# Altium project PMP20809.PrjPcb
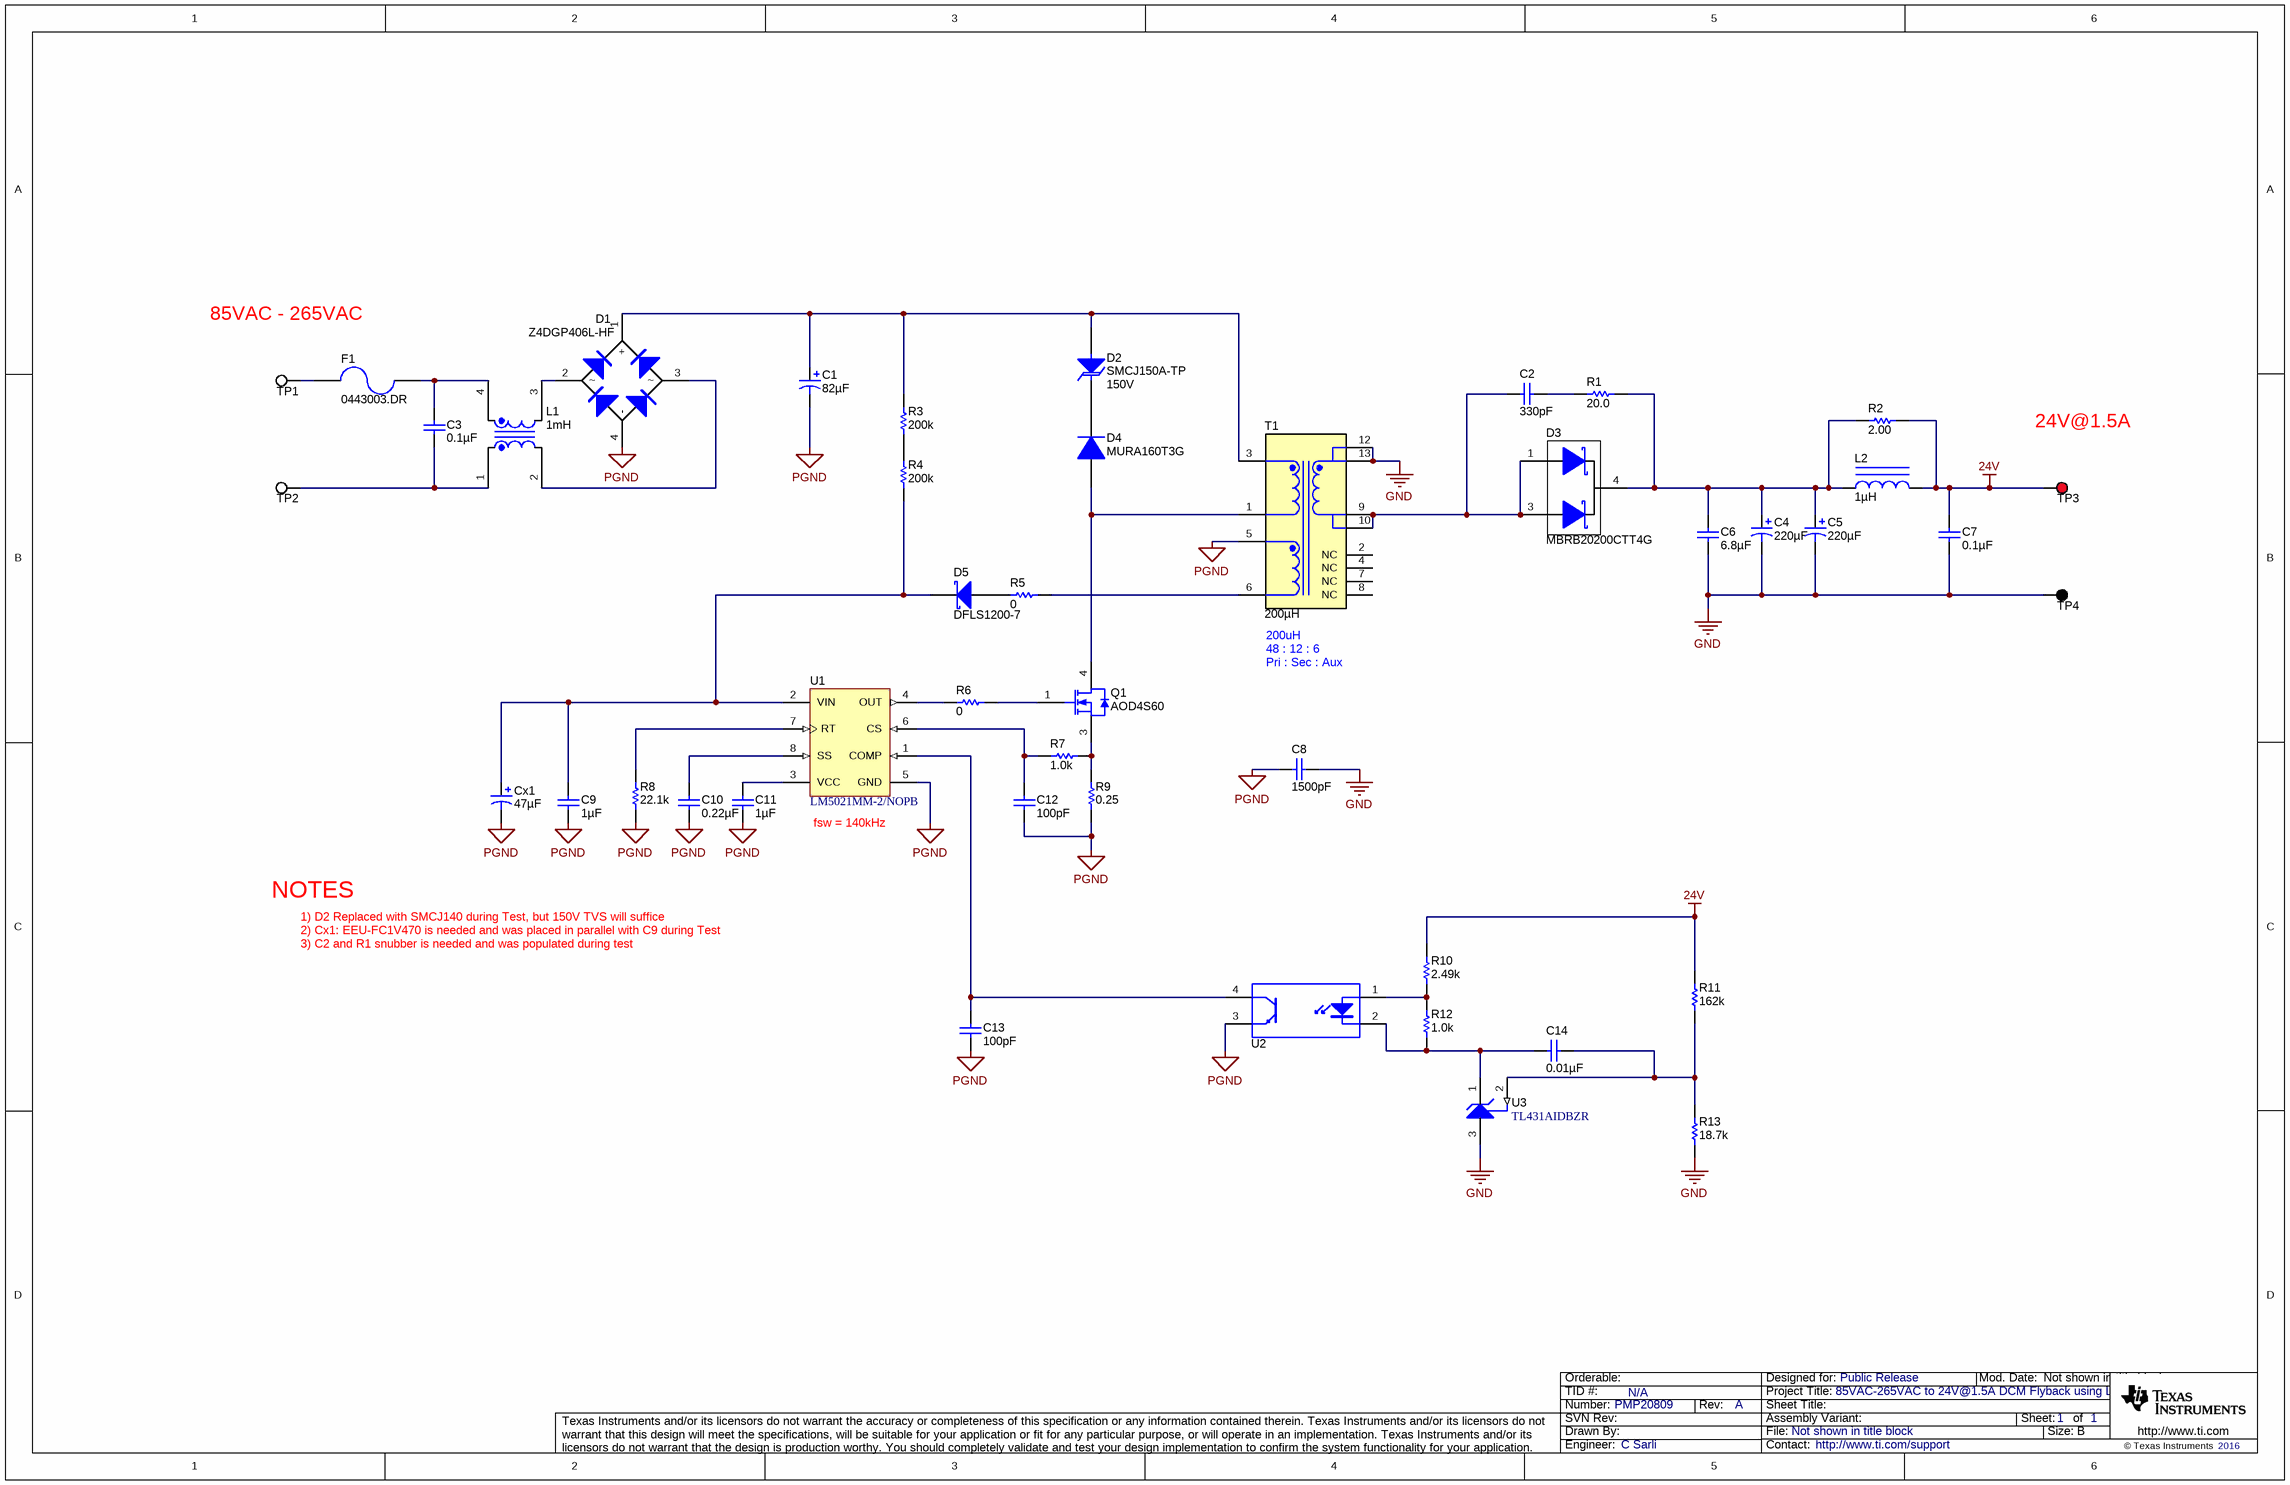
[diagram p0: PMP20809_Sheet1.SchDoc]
CopyrightYear: 2016; PCB_Layout: C Sarli; PCB_Rev: A; PRJ_Customer: Public Release; PRJ_Engineer: C Sarli; PRJ_Number: PMP20809; PRJ_Title: 85VAC-265VAC to 24V@1.5A DCM Flyback using LM5021; SCH_Rev: A; TechSupport: http://www.ti.com/support; TID: N/A
1 sheet, 45 parts. Net scope: global (net labels, ports and power ports of the same name join across sheets).
Board file: PMP20809_PCB.PcbDoc

## Sheet PMP20809_Sheet1.SchDoc
size 431 x 279 mm; Date: Not shown in title block; ApprovedBy: Not shown in title block; CheckedBy: Not shown in title block; Author: Not shown in title block; CompanyName: Not shown in title block; Engineer: Not shown in title block; Organization: Not shown in title block; Address1: Not shown in title block; Address2: Not shown in title block; Address3: Not shown in title block; Address4: Not shown in title block; DocumentNumber: 1; Revision: Use project parameter SCH_Rev; SheetNumber: 1; SheetTotal: 1; PageSetup: Record=PageOptions¦CenterHorizontal=True¦CenterVertical=True¦PrintScale=1.00¦XCorrection=1.00¦YCorrection=1.00¦PrintKind=0¦BorderSize=5000000¦LeftOffset=0¦BottomOffset=0¦Orientation=2¦PaperLength=1000¦PaperWidth=1000¦Scale=100¦PaperSource=15¦PrintQuality=600¦MediaType=1¦DitherType=10¦PaperKind=Letter¦PrintScaleMode=1

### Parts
C1  ValueDisplayed: 82µF  [Nichicon_2200x2500_Snap]  (hidden comment: LLS2G820MELZ)
C2  ValueDisplayed: 330pF  [1206]  (hidden comment: GRM31A5C2J331JW01D)
C3  ValueDisplayed: 0.1µF  [WCAP-FTX2_1800x600x1200]  (hidden comment: 890324025017)
C4  ValueDisplayed: 220µF  [Chemi-Con_1000x1250]  (hidden comment: EKZE350ELL221MJC5S)
C5  ValueDisplayed: 220µF  [Chemi-Con_1000x1250]  (hidden comment: EKZE350ELL221MJC5S)
C6  ValueDisplayed: 6.8µF  [0805_HV]  (hidden comment: C2012X5R1V685K125AC)
C7  ValueDisplayed: 0.1µF  [0603]  (hidden comment: C1608X5R1H104K080AA)
C8  ValueDisplayed: 1500pF  [KY_700x500x1000]  (hidden comment: DE2E3KY152MN3AM02F)
C9  ValueDisplayed: 1µF  [0603]  (hidden comment: GRM188R61H105KAALD)
C10  ValueDisplayed: 0.22µF  [0402]  (hidden comment: GRM155R71C224KA12D)
C11  ValueDisplayed: 1µF  [0402]  (hidden comment: GRM155R61E105KA12D)
C12  ValueDisplayed: 100pF  [0402]  (hidden comment: GRM1555C1H101JA01D)
C13  ValueDisplayed: 100pF  [0402]  (hidden comment: GRM1555C1H101JA01D)
C14  ValueDisplayed: 0.01µF  [0402]  (hidden comment: GRM155R71H103KA88D)
Cx1  ValueDisplayed: 47µF  [FC_630x1120]  (hidden comment: EEU-FC1V470)
D1  Z4DGP406L-HF  [Z4-D]
D2  SMCJ150A-TP  value 150V  [SMC]
D3  MBRB20200CTT4G  [DDPAK]
D4  MURA160T3G  [SMA]
D5  DFLS1200-7  [PowerDI123]
F1  0443003.DR  [FUSE_0443]
L1  ValueDisplayed: 1mH  [WE-CMB_XS]  (hidden comment: 744821201)
L2  ValueDisplayed: 1µH  [B82462G4]  (hidden comment: B82462G4102M)
Q1  AOD4S60  [DPAK]
R1  ValueDisplayed: 20.0  [1206]  (hidden comment: CRCW120620R0FKEA)
R2  ValueDisplayed: 2.00  [1206]  (hidden comment: CRCW12062R00FKEA)
R3  ValueDisplayed: 200k  [2010]  (hidden comment: CRCW2010200KJNEF)
R4  ValueDisplayed: 200k  [2010]  (hidden comment: CRCW2010200KJNEF)
R5  ValueDisplayed: 0  [0402]  (hidden comment: CRCW04020000Z0ED)
R6  ValueDisplayed: 0  [0603]  (hidden comment: CRCW06030000Z0EA)
R7  ValueDisplayed: 1.0k  [0402]  (hidden comment: CRCW04021K00JNED)
R8  ValueDisplayed: 22.1k  [0402]  (hidden comment: CRCW040222K1FKED)
R9  ValueDisplayed: 0.25  [1206]  (hidden comment: CSR1206FKR250)
R10  ValueDisplayed: 2.49k  [0402]  (hidden comment: CRCW04022K49FKED)
R11  ValueDisplayed: 162k  [0402]  (hidden comment: CRCW0402162KFKED)
R12  ValueDisplayed: 1.0k  [0603]  (hidden comment: CRCW06031K00JNEA)
R13  ValueDisplayed: 18.7k  [0402]  (hidden comment: CRCW040218K7FKED)
T1  ValueDisplayed: 200µH  [Renco_RLTI-1228]  (hidden comment: RLTI-1228)
TP1  5012  [Keystone5012]  (value not drawn)
TP2  5012  [Keystone5012]  (value not drawn)
TP3  5010  [Keystone5010]  (value not drawn)
TP4  5011  [Keystone5011]  (value not drawn)
U1  LM5021MM-2/NOPB  [MUA08A_N]
U2  VOS617A-7X001T  [SSOP-4_VISHAY]  (value not drawn)
U3  TL431AIDBZR  [DBZ0003A_N]

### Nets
24V: C7.1 L2.2 R2.2 R10.2 R11.2 TP3.1
GND: C4.2(-) C5.2(-) C6.2 C7.2 C8.1 R13.1 T1.12 T1.13 TP4.1 U3.3(ANODE)
PGND: C1.2(-) C8.2 C9.2 C10.2 C11.2 C12.2 C13.2 Cx1.2(-) D1.4(-) R8.1 R9.1 T1.5 U1.5(GND) U2.3(E)
NetC1_1: C1.1(+) D1.1(+) D2.2(A) R3.2 T1.3
NetC2_1: C2.1 R1.1
NetC2_2: C2.2 D3.1(A) D3.3(A) T1.9 T1.10
NetC3_1: C3.1 F1.1 L1.4
NetC3_2: C3.2 L1.1 TP2.1
NetC4_1: C4.1(+) C5.1(+) C6.1 D3.4(K) L2.1 R1.2 R2.1
NetC9_1: C9.1 Cx1.1(+) D5.1(K) R4.1 U1.2(VIN)
NetC10_1: C10.1 U1.8(SS)
NetC11_1: C11.1 U1.3(VCC)
NetC12_1: C12.1 R7.1 U1.6(CS)
NetC13_1: C13.1 U1.1(COMP) U2.4(C)
NetC14_1: C14.1 R11.1 R13.2 U3.2(REF)
NetC14_2: C14.2 R12.1 U2.2(K) U3.1(CATHODE)
NetD1_2: D1.2 L1.3
NetD1_3: D1.3 L1.2
NetD2_1: D2.1(K) D4.1(K)
NetD4_2: D4.2(A) Q1.4(D) T1.1
NetD5_2: D5.2(A) R5.1
NetF1_2: F1.2 TP1.1
NetQ1_1: Q1.1(G) R6.2
NetQ1_3: Q1.3(S) R7.2 R9.2
NetR3_1: R3.1 R4.2
NetR5_2: R5.2 T1.6
NetR6_1: R6.1 U1.4(OUT)
NetR8_2: R8.2 U1.7(RT)
NetR10_1: R10.1 R12.2 U2.1(A)

Not connected (* = marked no-connect by the designer): T1 2(NC) 4(NC) 7(NC) 8(NC)

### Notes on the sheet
- 85VAC - 265VAC
- 24V@1.5A
- (near T1) 200uH
- (near T1) 48 : 12 : 6
- Pri : Sec : Aux
- (near U1) fsw = 140kHz
- NOTES
- 1) D2 Replaced with SMCJ140 during Test, but 150V TVS will suffice
- 2) Cx1: EEU-FC1V470 is needed and was placed in parallel with C9 during Test
- 3) C2 and R1 snubber is needed and was populated during test

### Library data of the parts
C1 = LLS2G820MELZ: CAP, AL, 82 µF, 400 V, +/- 20%, TH; Manufacturer: Nichicon; Polarized: Y; CompType: Capacitor; Value: 82uF; U/M: EA; Cap_F: 0.000082; Tolerance_%: 20; Value1: Unknown; VDC_V: 400; Value2: 400V; IRMS_A: 0.84; TaMin_C: -25; TaMax_C: 85; Cap_Case: 22x25mm; SizeAreaWB_mm2: 576; SizeArea_mm2: 484; SizeX_mm: 22; SizeZ_mm: 27; AEC Category: Q200; AEC Qualified: N
C2 = GRM31A5C2J331JW01D: CAP, CERM, 330 pF, 630 V, +/- 5%, C0G/NP0, 1206; Manufacturer: MuRata; Polarized: N; CompType: Capacitor; Value: 330pF; U/M: EA; Cap_F: 0.00000000033; Tolerance_%: 5; Value1: Unknown; VDC_V: 630; Value2: 630V; TaMin_C: -55; TaMax_C: 125; SizeArea_mm2: 5.12; SizeAreaWB_mm2: 10.92; SizeX_mm: 3.2; SizeY_mm: 1.6; SizeZ_mm: 1.35; AEC Category: Q200
C3 = 890324025017: CAP, Film, 0.1 µF, 275 V, +/- 10%, TH; Manufacturer: Wurth Elektronik; Polarized: N; CompType: Capacitor; Value: 0.1uF; U/M: EA; Cap_F: 0.0000001; Tolerance_%: 10; Value1: Unknown; VDC_V: 275; Value2: 275V; TaMin_C: -40; TaMax_C: 105; Cap_Case: 18x6x12mm; AEC Category: Q200
C4 C5 = EKZE350ELL221MJC5S: CAP, AL, 220 µF, 35 V, +/- 20%, TH; Manufacturer: Chemi-Con; Polarized: Y; CompType: Capacitor; Value: 220uF; U/M: EA; Cap_F: 0.00022; Tolerance_%: 20; Value1: Unknown; VDC_V: 35; Value2: 35V; IRMS_A: 1.03; TaMin_C: -40; TaMax_C: 105; Cap_Case: 10x12.5; SizeAreaWB_mm2: 144; SizeArea_mm2: 100; SizeX_mm: 10; SizeZ_mm: 14; AEC Category: Q200; AEC Qualified: N
C6 = C2012X5R1V685K125AC: CAP, CERM, 6.8 µF, 35 V, +/- 10%, X5R, 0805; Manufacturer: TDK; Polarized: N; CompType: Capacitor; Value: 6.8uF; U/M: EA; Cap_F: 0.0000068; Tolerance_%: 10; ESR_ohm: 0.003795; Value1: 0.003795 ohm; VDC_V: 35; Value2: 35V; IRMS_A: 3.34931; TaMin_C: -55; TaMax_C: 85; Cap_Case: 0805; SizeArea_mm2: 2.5; SizeAreaWB_mm2: 6.75; SizeX_mm: 2; SizeY_mm: 1.25; SizeZ_mm: 1.45; AEC Category: Q200
C7 = C1608X5R1H104K080AA: CAP, CERM, 0.1 µF, 50 V, +/- 10%, X5R, 0603; Manufacturer: TDK; Polarized: N; CompType: Capacitor; Value: 0.1uF; U/M: EA; Cap_F: 0.0000001; Tolerance_%: 10; ESR_ohm: 0.0296; Value1: 0.0296 ohm; VDC_V: 50; Value2: 50V; IRMS_A: 0.97199; TaMin_C: -55; TaMax_C: 85; SizeArea_mm2: 1.28; SizeAreaWB_mm2: 4.68; SizeX_mm: 1.6; SizeY_mm: 0.8; SizeZ_mm: 1; AEC Category: Q200
C8 = DE2E3KY152MN3AM02F: CAP, CERM, 1500 pF,  V, +/- 20%, E, TH, 2- Leads, Body 7x5mm, Pin Spacing 7.5mm; Manufacturer: MuRata; Polarized: N; CompType: Capacitor; Value: 1500pF; U/M: EA; Cap_F: 0.0000000015; Tolerance_%: 20; Value1: Unknown; TaMin_C: -25; TaMax_C: 85; Cap_Case: 7x5x10mm; SizeArea_mm2: 37.5; SizeAreaWB_mm2: 66.5; SizeX_mm: 7.5; SizeY_mm: 5; SizeZ_mm: 10; AEC Category: Q200
C9 = GRM188R61H105KAALD: CAP, CERM, 1 µF, 50 V, +/- 10%, X5R, 0603; Manufacturer: MuRata; Polarized: N; CompType: Capacitor; Value: 1uF; U/M: EA; Cap_F: 0.000001; Tolerance_%: 10; Value1: Unknown; VDC_V: 50; Value2: 50V; TaMin_C: -55; TaMax_C: 85; SizeArea_mm2: 1.28; SizeAreaWB_mm2: 4.68; SizeX_mm: 1.6; SizeY_mm: 0.8; SizeZ_mm: 1; AEC Category: Q200
C10 = GRM155R71C224KA12D: CAP, CERM, 0.22 µF, 16 V, +/- 10%, X7R, 0402; Manufacturer: MuRata; Polarized: N; CompType: Capacitor; Value: 0.22uF; U/M: EA; Cap_F: 0.00000022; Tolerance_%: 10; Value1: Unknown; VDC_V: 16; Value2: 16V; TaMin_C: -55; TaMax_C: 125; SizeArea_mm2: 0.5; SizeAreaWB_mm2: 3; SizeX_mm: 1; SizeZ_mm: 0.6; AEC Category: Q200
C11 = GRM155R61E105KA12D: CAP, CERM, 1 µF, 25 V, +/- 10%, X5R, 0402; Manufacturer: MuRata; Polarized: N; CompType: Capacitor; Value: 1uF; U/M: EA; Cap_F: 0.000001; Tolerance_%: 10; Value1: Unknown; VDC_V: 25; Value2: 25V; TaMin_C: -55; TaMax_C: 85; SizeArea_mm2: 0.5; SizeAreaWB_mm2: 3; SizeX_mm: 1; SizeZ_mm: 0.6; AEC Category: Q200
C12 C13 = GRM1555C1H101JA01D: CAP, CERM, 100 pF, 50 V, +/- 5%, C0G/NP0, 0402; Manufacturer: MuRata; Polarized: N; CompType: Capacitor; Value: 100pF; U/M: EA; Cap_F: 0.0000000001; Tolerance_%: 5; Value1: Unknown; VDC_V: 50; Value2: 50V; TaMin_C: -55; TaMax_C: 125; SizeArea_mm2: 0.5; SizeAreaWB_mm2: 3; SizeX_mm: 1; SizeZ_mm: 0.6; AEC Category: Q200
C14 = GRM155R71H103KA88D: CAP, CERM, 0.01 µF, 50 V, +/- 10%, X7R, 0402; Manufacturer: MuRata; Polarized: N; CompType: Capacitor; Value: 0.01uF; U/M: EA; Cap_F: 0.00000001; Tolerance_%: 10; Value1: Unknown; VDC_V: 50; Value2: 50V; TaMin_C: -55; TaMax_C: 125; SizeArea_mm2: 0.5; SizeAreaWB_mm2: 3; SizeX_mm: 1; SizeZ_mm: 0.6; AEC Category: Q200
Cx1 = EEU-FC1V470: CAP, AL, 47 µF, 35 V, +/- 20%, AEC-Q200 Grade 2, TH; Manufacturer: Panasonic; Polarized: Y; CompType: Capacitor; Value: 47uF; U/M: EA; Cap_F: 0.000047; Tolerance_%: 20; Value1: Unknown; VDC_V: 35; Value2: 35V; IRMS_A: 0.29; TaMin_C: -55; TaMax_C: 105; Cap_Case: 6.3x11.2mm; SizeAreaWB_mm2: 68.89; SizeArea_mm2: 39.69; SizeX_mm: 6.3; SizeZ_mm: 12.2; AEC Category: Q200; AEC Grade: 2
D1 = Z4DGP406L-HF: Diode, P-N-Bridge, 600 V, 4 A, Z4-D; Manufacturer: Comchip Technology; U/M: EA; Vf_V: 0.95; Value: 600V; Value1: 4A; Value2: 0.95V; Io_A: 4; Vr_V: 600; TJmax_C: 175; SizeAreaWB_mm2: 126.25; SizeArea_mm2: 85.05; SizeX_mm: 10.5; SizeY_mm: 8.1; SizeZ_mm: 1.55; AEC Category: Q101; AEC Qualified: N
D2 = SMCJ150A-TP: Diode, TVS, Uni, 150 V, 243 Vc, SMC; Manufacturer: Micro Commercial Components; U/M: EA; Vr_V: 150; Value1: W; SizeAreaWB_mm2: 83.2686; SizeArea_mm2: 50.5686; SizeX_mm: 8.13; SizeY_mm: 6.22; SizeZ_mm: 2.6; AEC Category: Q101; AEC Qualified: N
D3 = MBRB20200CTT4G: Diode, Schottky, 200 V, 20 A, DDPAK; Manufacturer: ON Semiconductor; U/M: EA; Vf_V: 1; Value: 200V; Value1: 20A; Value2: 1V; Io_A: 20; Vr_V: 200; TJmax_C: 150; RJC_CperW: 2; SizeAreaWB_mm2: 209.6992; SizeArea_mm2: 154.8892; SizeX_mm: 15.245; SizeY_mm: 10.16; SizeZ_mm: 4.445; AEC Category: Q101
D4 = MURA160T3G: Diode, Ultrafast, 600 V, 1 A, AEC-Q101, SMA; Manufacturer: ON Semiconductor; U/M: EA; Vf_V: 1.05; Value: 600V; Value1: 1A; Value2: 1.05V; Io_A: 1; Vr_V: 600; TJmax_C: 175; SizeAreaWB_mm2: 37.3428; SizeArea_mm2: 16.3228; SizeX_mm: 5.59; SizeY_mm: 2.92; SizeZ_mm: 2.87; AEC Category: Q101; AEC Qualified: Y
D5 = DFLS1200-7: Diode, Schottky, 200 V, 1 A, PowerDI123; Manufacturer: Diodes Inc.; U/M: EA; Vf_V: 0.85; Value: 200V; Value1: 1A; Value2: 0.85V; Io_A: 1; Vr_V: 200; TJmax_C: 175; RJC_CperW: 7; SizeAreaWB_mm2: 13.066; SizeArea_mm2: 6.586; SizeX_mm: 3.7; SizeY_mm: 1.78; SizeZ_mm: 0.98; AEC Category: Q101
F1 = 0443003.DR: Fuse, 3 A, 250VAC/VDC, SMD; Manufacturer: Littelfuse; VDC_V: 250; Interrupt_AC: 50; Irating_A: 3; Rtyp_Ohm: 0.028; MeltingTyp: 51.44
L1 = 744821201: Coupled inductor, 1 mH, 2 A, 0.045 ohm, TH; Manufacturer: Wurth Elektronik; SymbolCreator: a0412235; SizeAreaWB_mm2: 161.5; SizeArea_mm2: 112.5; SizeX_mm: 15; SizeY_mm: 7.5; SizeZ_mm: 20.5; Value: 1mH; Ind_H: 1.0E-3; DCR_ohm: 0.045
L2 = B82462G4102M: Inductor, Shielded Drum Core, Ferrite, 1 µH, 3.4 A, 0.016 ohm, AEC-Q200 Grade 0, SMD; Manufacturer: TDK; Value: 1uH; Ind_H: 1.0E-6; Imax_A: 3.4; Irms: 3.4A @ 40C rise; Isat: 4.4A @ 10% inductance drop; DCR_ohm: 0.016; Value2: 3.4A; SizeAreaWB_mm2: 68.89; SizeArea_mm2: 39.69; SizeX_mm: 6.3; SizeZ_mm: 3; AEC Category: Q200; AEC Qualified: Y; AEC Grade: 0
Q1 = AOD4S60: MOSFET, N-CH, 600 V, 4 A, DPAK; Manufacturer: AOS; Alternate Manufacturer: None; U/M: EA; ChType: N; Value: 600V; VdsMax_V: 600; Value1: ? ohm; Value2: 6 nC; QgTyp_nC: 6; Vgs_V: 30; IdsMax_A: 4; SizeAreaWB_mm2: 101.7114; SizeArea_mm2: 64.8114; SizeX_mm: 9.91; SizeY_mm: 6.54; SizeZ_mm: 2.29; AEC Category: Q101
R1 = CRCW120620R0FKEA: RES, 20.0, 1%, 0.25 W, 1206; Manufacturer: Vishay-Dale; CompType: Resistor; Value: 20.0; Res_ohm: 20; Value_Code: 20R0; Tolerance_%: 1; Power_W: 0.25; Value2: 0.25W; VDC_V: 200; TempCo: 100 ppm/C; SizeArea_mm2: 5.12; SizeX_mm: 3.2; SizeY_mm: 1.6; SizeZ_mm: 1.35; EIA_Code: E96; U/M: EA; AEC Category: Q200
R2 = CRCW12062R00FKEA: RES, 2.00, 1%, 0.25 W, 1206; Manufacturer: Vishay-Dale; CompType: Resistor; Value: 2.00; Res_ohm: 2; Value_Code: 2R00; Tolerance_%: 1; Power_W: 0.25; Value2: 0.25W; VDC_V: 200; TempCo: 100 ppm/C; SizeArea_mm2: 5.12; SizeX_mm: 3.2; SizeY_mm: 1.6; SizeZ_mm: 1.35; EIA_Code: E96; U/M: EA; AEC Category: Q200
R3 R4 = CRCW2010200KJNEF: RES, 200 k, 5%, 0.75 W, AEC-Q200 Grade 0, 2010; Manufacturer: Vishay-Dale; CompType: Resistor; Value: 200k; Res_ohm: 200000; Tolerance_%: 5; Power_W: 0.75; Value2: 0.75W; VDC_V: 400; TempCo: 200 ppm/C; SizeArea_mm2: 12.5; SizeY_mm: 2.5; SizeZ_mm: 1.66; EIA_Code: E24; U/M: EA; AEC Category: Q200; AEC Qualified: Y; AEC Grade: 0
R5 = CRCW04020000Z0ED: RES, 0, 5%, 0.063 W, 0402; Manufacturer: Vishay-Dale; CompType: Resistor; Value: 0; Value_Code: 0000; Tolerance_%: 5; Power_W: 0.063; Value2: 0.063W; VDC_V: 50; TempCo: 200 ppm/C; SizeArea_mm2: 0.5; SizeX_mm: 1; SizeZ_mm: 0.6; EIA_Code: E24; U/M: EA; AEC Category: Q200
R6 = CRCW06030000Z0EA: RES, 0, 5%, 0.1 W, 0603; Manufacturer: Vishay-Dale; CompType: Resistor; Value: 0; Value_Code: 0000; Tolerance_%: 5; Power_W: 0.1; Value2: 0.1W; VDC_V: 75; TempCo: 200 ppm/C; SizeArea_mm2: 1.28; SizeX_mm: 1.6; SizeY_mm: 0.8; SizeZ_mm: 1; EIA_Code: E24; U/M: EA; AEC Category: Q200
R7 = CRCW04021K00JNED: RES, 1.0 k, 5%, 0.063 W, 0402; Manufacturer: Vishay-Dale; CompType: Resistor; Value: 1.0k; Res_ohm: 1000; Value_Code: 1k00; Tolerance_%: 5; Power_W: 0.063; Value2: 0.063W; VDC_V: 50; TempCo: 200 ppm/C; SizeArea_mm2: 0.5; SizeX_mm: 1; SizeZ_mm: 0.6; EIA_Code: E24; U/M: EA; AEC Category: Q200
R8 = CRCW040222K1FKED: RES, 22.1 k, 1%, 0.063 W, 0402; Manufacturer: Vishay-Dale; CompType: Resistor; Value: 22.1k; Res_ohm: 22100; Value_Code: 22k1; Tolerance_%: 1; Power_W: 0.063; Value2: 0.063W; VDC_V: 50; TempCo: 100 ppm/C; SizeArea_mm2: 0.5; SizeZ_mm: 0.6; EIA_Code: E96; U/M: EA; AEC Category: Q200
R9 = CSR1206FKR250: RES, 0.25, 1%, 0.5 W, 1206; Manufacturer: Stackpole Electronics Inc; CompType: Resistor; Value: 0.25; Value_Code: R250; Tolerance_%: 1; Power_W: 0.5; Value2: 0.5W; TempCo: 100 ppm/C; SizeArea_mm2: 5.12; SizeX_mm: 3.2; SizeY_mm: 1.6; SizeZ_mm: 1.35; U/M: EA; AEC Category: Q200
R10 = CRCW04022K49FKED: RES, 2.49 k, 1%, 0.063 W, 0402; Manufacturer: Vishay-Dale; CompType: Resistor; Value: 2.49k; Res_ohm: 2490; Value_Code: 2k49; Tolerance_%: 1; Power_W: 0.063; Value2: 0.063W; VDC_V: 50; TempCo: 100 ppm/C; SizeArea_mm2: 0.5; SizeZ_mm: 0.6; EIA_Code: E96; U/M: EA; AEC Category: Q200
R11 = CRCW0402162KFKED: RES, 162 k, 1%, 0.063 W, 0402; Manufacturer: Vishay-Dale; CompType: Resistor; Value: 162k; Res_ohm: 162000; Tolerance_%: 1; Power_W: 0.063; Value2: 0.063W; VDC_V: 50; TempCo: 100 ppm/C; SizeArea_mm2: 0.5; SizeZ_mm: 0.6; EIA_Code: E96; U/M: EA; AEC Category: Q200
R12 = CRCW06031K00JNEA: RES, 1.0 k, 5%, 0.1 W, 0603; Manufacturer: Vishay-Dale; CompType: Resistor; Value: 1.0k; Res_ohm: 1000; Value_Code: 1k00; Tolerance_%: 5; Power_W: 0.1; Value2: 0.1W; VDC_V: 75; TempCo: 200 ppm/C; SizeArea_mm2: 1.28; SizeX_mm: 1.6; SizeY_mm: 0.8; SizeZ_mm: 1; EIA_Code: E24; U/M: EA; AEC Category: Q200
R13 = CRCW040218K7FKED: RES, 18.7 k, 1%, 0.063 W, 0402; Manufacturer: Vishay-Dale; CompType: Resistor; Value: 18.7k; Res_ohm: 18700; Value_Code: 18k7; Tolerance_%: 1; Power_W: 0.063; Value2: 0.063W; VDC_V: 50; TempCo: 100 ppm/C; SizeArea_mm2: 0.5; SizeZ_mm: 0.6; EIA_Code: E96; U/M: EA; AEC Category: Q200
T1 = RLTI-1228: Transformer, 200 uH, TH; Manufacturer: Renco Electronics; SymbolCreator: Altium; Value: 200uH; Lp: 200; DCR_ohm: 0.39; Ns1toNp: 0.25; Rs1: 0.006; SizeAreaWB_mm2: 690.0260092; SizeArea_mm2: 588.9472092; SizeX_mm: 24.5364; SizeY_mm: 24.003; SizeZ_mm: 23.495
TP1 TP2 = 5012: Test Point, Multipurpose, White, TH; Manufacturer: Keystone; CompType: Test Point Loop; ContactFinish: Silver
TP3 = 5010: Test Point, Multipurpose, Red, TH; Manufacturer: Keystone; CompType: Test Point Loop; ContactFinish: Silver
TP4 = 5011: Test Point, Multipurpose, Black, TH; Manufacturer: Keystone; CompType: Test Point Loop; ContactFinish: Silver
U1 = LM5021MM-2/NOPB: AC-DC Current Mode PWM Controller, 8-pin MSOP, Pb-Free; Manufacturer: Texas Instruments; PackageTopMarking: ZXTT*21-2; PowerWise: N; CompType: Switcher
U2 = VOS617A-7X001T: Optocoupler, 3.75 kV, 80-160% CTR, SMT; Manufacturer: Vishay-Semiconductor; CTR (Min): 80%; CTR (Max): 160%; Voltage_Isolation_Vrms: 3750V
U3 = TL431AIDBZR: Adjustable Precision Shunt Regulator, 34 ppm / degC, 100 mA, -40 to 85 degC, 3-pin SOT-23 (DBZ), Green (RoHS & no Sb/Br); Manufacturer: Texas Instruments; Alternate PartNumber: Equivalent; Initial Accuracy @ 25/deg C(%): 1; Iout/Iz(Max)(mA): 100; Min Iz for Regulation(uA): 600; Rating: Catalog; SubFamily: Shunt Voltage Reference; Temp Coeff(Max)(ppm/ degree C): 92; Temp Coeff(Typ)(ppm/ degree C): 34; VO Adj(Max)(V): 36; VO Adj(Min)(V): 2.495

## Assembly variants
001: all parts fitted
